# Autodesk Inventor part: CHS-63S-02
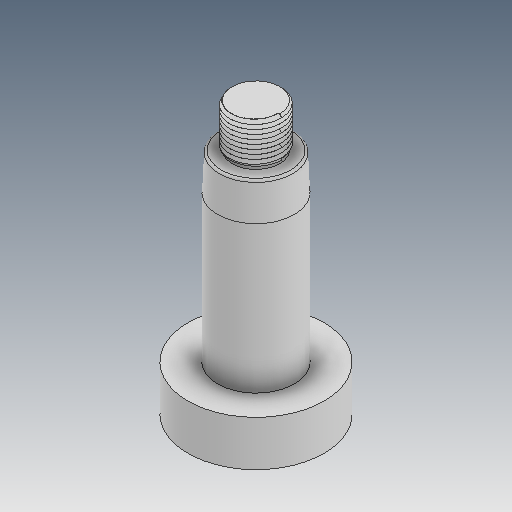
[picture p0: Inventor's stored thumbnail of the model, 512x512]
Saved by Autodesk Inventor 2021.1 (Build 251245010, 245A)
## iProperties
Created: 2019-05
Part Number: CHS-63S-02
Material: Ogólny
Document SubType Name: Modeling
Designer: user
Density: 1 g/cm^3
Appearance: Domyślna
Author: user
Revision Number: ÈÎºÎ
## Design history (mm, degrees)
feature "ÊäÈë1"
feature "ÊäÈë2"
node "Bryła1"
node "Bryła2"
